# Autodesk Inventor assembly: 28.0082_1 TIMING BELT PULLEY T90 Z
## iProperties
Created: 2007-04
Part Number: 28.0082_1 TIMING BELT PULLEY T90 Z
Document SubType Name: Assembly
Designer: Andy Moles
Author: Andy Moles
